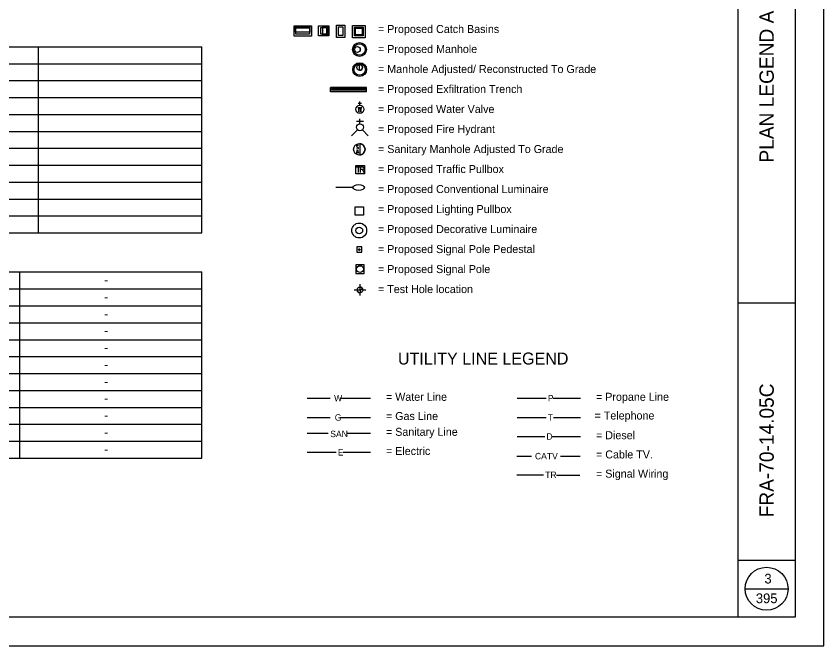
# Model space of a CAD drawing. Extents: x 0 to 34, y 0 to 22.
# Drawn here: x 19.88 to 34, y 0 to 11.02 of the extents above; entities that cross this region are included whole.
import ezdxf

# ---------------------------------------------------------------- set-up
doc = ezdxf.new("R2010")
doc.units = 0
for name, color, linetype in [('Default', 7, 'Continuous'), ('DR_P_Cells', 7, 'Continuous'), ('DR_P_Storm_Sewer', 7, 'Continuous'), ('LT_P_Luminaires', 7, 'Continuous'), ('SG_P_Poles', 7, 'Continuous'), ('SG_P_PullBox', 7, 'Continuous'), ('SH_Border', 7, 'Continuous'), ('SH_Cut_Line', 7, 'Continuous'), ('SH_Data', 7, 'Continuous'), ('SH_Text', 7, 'Continuous'), ('TX_P_5', 7, 'Continuous'), ('TX_P_Misc', 7, 'Continuous'), ('UT_P_Sanitary_Cells', 7, 'Continuous'), ('UT_P_Water_Cells', 7, 'Continuous')]:
    doc.layers.add(name, color=color, linetype=linetype)

msp = doc.modelspace()

# ---------------------------------------------------------------- linework, layer by layer
at = {"layer": 'Default'}
for p, q in [((24.969, 4.334), (25.372, 4.334)), ((25.547, 4.334), (26.075, 4.334)), ((28.641, 4.333), (29.147, 4.333)), ((29.271, 4.333), (29.747, 4.333)), ((24.969, 3.998), (25.372, 3.998)), ((25.547, 3.998), (26.075, 3.998)), ((28.641, 3.997), (29.145, 3.997)), ((29.272, 3.997), (29.747, 3.997)), ((24.969, 3.722), (25.334, 3.722)), ((25.672, 3.722), (26.075, 3.722)), ((28.641, 3.663), (29.122, 3.663)), ((29.245, 3.663), (29.747, 3.663)), ((24.969, 3.386), (25.474, 3.386)), ((25.597, 3.386), (26.075, 3.386)), ((28.633, 3.32), (28.889, 3.32)), ((29.394, 3.32), (29.739, 3.32)), ((28.634, 2.994), (29.101, 2.994)), ((29.329, 2.989), (29.736, 2.989))]:
    msp.add_line(p, q, dxfattribs=at)
msp.add_lwpolyline([(25.805, 7.683), (25.955, 7.683), (25.955, 7.533), (25.805, 7.533)], close=True, dxfattribs=at)
at = {"layer": 'DR_P_Cells'}
for p, q in [((24.773, 10.777), (24.773, 10.814)), ((24.773, 10.814), (24.833, 10.814)), ((24.773, 10.758), (24.773, 10.758)), ((24.871, 10.814), (24.913, 10.814)), ((24.892, 10.848), (24.892, 10.848)), ((24.892, 10.814), (24.892, 10.814)), ((24.892, 10.758), (24.892, 10.758)), ((24.892, 10.739), (24.892, 10.739)), ((24.892, 10.739), (24.892, 10.739)), ((24.951, 10.814), (25.011, 10.814)), ((25.011, 10.814), (25.011, 10.777)), ((25.011, 10.758), (25.011, 10.758)), ((25.169, 10.759), (25.169, 10.759)), ((25.203, 10.759), (25.203, 10.759)), ((25.24, 10.759), (25.24, 10.759)), ((25.24, 10.759), (25.24, 10.759)), ((25.259, 10.814), (25.259, 10.814)), ((25.259, 10.759), (25.259, 10.759)), ((25.259, 10.759), (25.259, 10.759)), ((25.315, 10.759), (25.315, 10.759)), ((25.349, 10.759), (25.349, 10.759)), ((25.483, 10.754), (25.483, 10.754)), ((25.516, 10.754), (25.516, 10.754)), ((25.516, 10.754), (25.516, 10.754)), ((25.516, 10.754), (25.516, 10.754)), ((25.554, 10.829), (25.554, 10.829)), ((25.554, 10.754), (25.554, 10.754)), ((25.591, 10.754), (25.591, 10.754)), ((25.624, 10.754), (25.624, 10.754)), ((25.763, 10.747), (25.763, 10.747)), ((25.796, 10.747), (25.796, 10.747)), ((25.871, 10.822), (25.871, 10.822)), ((25.871, 10.747), (25.871, 10.747)), ((25.871, 10.747), (25.871, 10.747)), ((25.871, 10.747), (25.871, 10.747)), ((25.946, 10.747), (25.946, 10.747)), ((25.98, 10.747), (25.98, 10.747)), ((24.892, 10.702), (24.892, 10.702)), ((24.892, 10.669), (24.892, 10.669)), ((25.259, 10.705), (25.259, 10.705)), ((25.554, 10.679), (25.554, 10.679)), ((25.871, 10.672), (25.871, 10.672)), ((25.783, 10.433), (25.783, 10.433)), ((25.846, 10.434), (25.846, 10.434)), ((25.883, 10.434), (25.883, 10.434)), ((25.883, 10.434), (25.883, 10.434)), ((25.983, 10.436), (25.983, 10.436)), ((25.886, 10.182), (25.886, 10.182)), ((25.886, 10.07), (25.886, 10.17)), ((25.886, 10.12), (25.886, 10.12)), ((25.886, 10.082), (25.886, 10.082)), ((25.886, 10.082), (25.886, 10.082)), ((25.886, 9.982), (25.886, 9.982))]:
    msp.add_line(p, q, dxfattribs=at)
for points in [[(25.044, 10.669), (24.74, 10.669), (24.74, 10.848), (25.044, 10.848)], [(25.017, 10.739), (24.767, 10.739), (24.767, 10.831), (25.017, 10.831)], [(25.011, 10.702), (24.773, 10.702), (24.773, 10.814), (25.011, 10.814)], [(25.169, 10.672), (25.169, 10.847), (25.349, 10.847), (25.349, 10.672)], [(25.203, 10.814), (25.203, 10.705), (25.315, 10.705), (25.315, 10.814)], [(25.24, 10.689), (25.24, 10.83), (25.332, 10.83), (25.332, 10.689)], [(25.483, 10.646), (25.483, 10.862), (25.624, 10.862), (25.624, 10.646)], [(25.516, 10.679), (25.516, 10.829), (25.591, 10.829), (25.591, 10.679)], [(25.516, 10.679), (25.516, 10.829), (25.591, 10.829), (25.591, 10.679)], [(25.516, 10.679), (25.516, 10.829), (25.591, 10.829), (25.591, 10.679)], [(25.763, 10.638), (25.763, 10.855), (25.98, 10.855), (25.98, 10.638)], [(25.796, 10.672), (25.796, 10.822), (25.946, 10.822), (25.946, 10.672)], [(25.814, 10.689), (25.814, 10.804), (25.929, 10.804), (25.929, 10.689)]]:
    msp.add_lwpolyline(points, close=True, dxfattribs=at)
for centre, radius in [((25.883, 10.434), 0.121), ((25.883, 10.434), 0.1), ((25.883, 10.434), 0.1), ((25.846, 10.434), 0.05), ((25.886, 10.082), 0.121), ((25.886, 10.082), 0.1), ((25.886, 10.082), 0.1), ((25.886, 10.12), 0.05)]:
    msp.add_circle(centre, radius, dxfattribs=at)
msp.add_arc((25.886, 10.12), 0.05, 270, 90, dxfattribs=at)
at = {"layer": 'DR_P_Storm_Sewer'}
for p, q in [((26.007, 9.77), (25.374, 9.77)), ((25.374, 9.695), (25.374, 9.77)), ((26.007, 9.695), (26.007, 9.77)), ((26.007, 9.695), (25.374, 9.695)), ((25.991, 9.72), (25.391, 9.72)), ((25.991, 9.72), (25.624, 9.72))]:
    msp.add_line(p, q, dxfattribs=at)
msp.add_lwpolyline([(25.991, 9.753), (25.991, 9.72), (25.391, 9.72), (25.391, 9.753)], close=True, dxfattribs=at)
at = {"layer": 'LT_P_Luminaires'}
msp.add_line((25.769, 8.019), (25.469, 8.019), dxfattribs=at)
for radius in [0.13, 0.06]:
    msp.add_circle((25.878, 7.267), radius, dxfattribs=at)
msp.add_ellipse((25.869, 8.019), major_axis=(-0.1, 0), ratio=0.5, dxfattribs=at)
msp.add_ellipse((25.869, 8.019), major_axis=(-0.1, 0), ratio=0.5, dxfattribs=at)
at = {"layer": 'SG_P_Poles'}
for points in [[(25.836, 6.889), (25.926, 6.889), (25.926, 6.979), (25.836, 6.979)], [(25.817, 6.516), (25.967, 6.516), (25.967, 6.666), (25.817, 6.666)]]:
    msp.add_lwpolyline(points, close=True, dxfattribs=at)
for centre, radius in [((25.881, 6.934), 0.015), ((25.892, 6.591), 0.06)]:
    msp.add_circle(centre, radius, dxfattribs=at)
at = {"layer": 'SG_P_PullBox'}
msp.add_line((25.895, 8.331), (25.895, 8.331), dxfattribs=at)
msp.add_lwpolyline([(25.82, 8.406), (25.97, 8.406), (25.97, 8.256), (25.82, 8.256)], close=True, dxfattribs=at)
for points in [[(25.827, 8.381), (25.889, 8.381)], [(25.858, 8.381), (25.858, 8.281)], [(25.9, 8.281), (25.9, 8.381), (25.938, 8.381), (25.942, 8.38), (25.947, 8.379), (25.95, 8.377), (25.952, 8.375), (25.955, 8.371), (25.958, 8.368), (25.959, 8.361), (25.959, 8.352), (25.958, 8.349), (25.957, 8.344), (25.954, 8.338), (25.951, 8.336), (25.948, 8.334), (25.947, 8.334), (25.944, 8.333), (25.937, 8.332), (25.9, 8.332)], [(25.937, 8.332), (25.959, 8.281)]]:
    msp.add_lwpolyline(points, dxfattribs=at)
at = {"layer": 'SH_Border'}
for p, q in [((32.5, 0.5), (32.5, 21.5)), ((32.5, 6), (33.5, 6)), ((32.5, 1.5), (33.5, 1.5))]:
    msp.add_line(p, q, dxfattribs=at)
msp.add_lwpolyline([(2, 21.5), (33.5, 21.5), (33.5, 0.5), (2, 0.5)], close=True, dxfattribs=at)
at = {"layer": 'SH_Cut_Line'}
msp.add_lwpolyline([(0, 0), (34, 0), (34, 22), (0, 22)], close=True, dxfattribs=at)
at = {"layer": 'SH_Data'}
msp.add_line((32.625, 1), (33.375, 1), dxfattribs=at)
msp.add_circle((33, 1), 0.375, dxfattribs=at)
at = {"layer": 'TX_P_5'}
for p, q in [((8.165, 10.481), (23.127, 10.481)), ((20.27, 7.225), (20.27, 10.481)), ((23.127, 7.225), (23.127, 10.481)), ((8.165, 10.185), (23.127, 10.185)), ((8.165, 9.889), (23.127, 9.889)), ((8.165, 9.593), (23.127, 9.593)), ((8.165, 9.297), (23.127, 9.297)), ((8.165, 9.001), (23.127, 9.001)), ((8.165, 8.705), (23.127, 8.705)), ((8.165, 8.409), (23.127, 8.409)), ((8.165, 8.113), (23.127, 8.113)), ((8.165, 7.817), (23.127, 7.817)), ((8.165, 7.521), (23.127, 7.521)), ((8.165, 7.225), (23.127, 7.225)), ((8.165, 6.541), (23.127, 6.541)), ((19.946, 3.285), (19.946, 6.541)), ((23.127, 3.285), (23.127, 6.541)), ((8.165, 6.245), (23.127, 6.245)), ((8.165, 5.949), (23.127, 5.949)), ((8.165, 5.653), (23.127, 5.653)), ((8.165, 5.357), (23.127, 5.357)), ((8.165, 5.061), (23.127, 5.061)), ((8.165, 4.765), (23.127, 4.765)), ((8.165, 4.469), (23.127, 4.469)), ((8.165, 4.173), (23.127, 4.173)), ((8.165, 3.877), (23.127, 3.877)), ((8.165, 3.581), (23.127, 3.581)), ((8.165, 3.285), (23.127, 3.285))]:
    msp.add_line(p, q, dxfattribs=at)
at = {"layer": 'TX_P_Misc'}
for p, q in [((25.791, 6.227), (25.841, 6.227)), ((25.841, 6.227), (25.892, 6.227)), ((25.892, 6.277), (25.892, 6.327)), ((25.892, 6.227), (25.892, 6.277)), ((25.892, 6.227), (25.892, 6.177)), ((25.941, 6.227), (25.892, 6.227)), ((25.941, 6.227), (25.991, 6.227)), ((25.892, 6.127), (25.892, 6.177))]:
    msp.add_line(p, q, dxfattribs=at)
msp.add_circle((25.892, 6.227), 0.05, dxfattribs=at)
for start, end in [(179.7135, 270.2865), (0.2865, 89.7135)]:
    msp.add_arc((25.891, 6.227), 0.05, start, end, dxfattribs=at)
at = {"layer": 'UT_P_Sanitary_Cells'}
for p, q in [((25.89, 8.787), (25.89, 8.588)), ((25.833, 8.633), (25.862, 8.633)), ((25.835, 8.734), (25.862, 8.72))]:
    msp.add_line(p, q, dxfattribs=at)
msp.add_lwpolyline([(25.828, 8.618), (25.847, 8.678), (25.867, 8.618)], dxfattribs=at)
msp.add_circle((25.88, 8.687), 0.1, dxfattribs=at)
for centre, radius, start, end in [((25.849, 8.724), 0.0314, 61.3463, 118.6537), ((25.88, 8.687), 0.1, 275.7389, 84.2597), ((25.841, 8.743), 0.0106, 126.2587, 236.3675), ((25.848, 8.721), 0.0249, 223.6695, 304.3963), ((25.853, 8.71), 0.0133, 311.4883, 47.9358)]:
    msp.add_arc(centre, radius, start, end, dxfattribs=at)
at = {"layer": 'UT_P_Water_Cells'}
for p, q in [((25.921, 9.489), (25.858, 9.489)), ((25.889, 9.457), (25.889, 9.521)), ((25.891, 9.132), (25.891, 9.218)), ((25.951, 9.175), (25.831, 9.175)), ((25.849, 9.029), (25.745, 8.925)), ((25.933, 9.029), (26.037, 8.925))]:
    msp.add_line(p, q, dxfattribs=at)
msp.add_lwpolyline([(25.858, 9.427), (25.874, 9.341), (25.889, 9.427), (25.905, 9.341), (25.921, 9.427)], dxfattribs=at)
for centre, radius in [((25.889, 9.387), 0.07), ((25.891, 9.072), 0.06)]:
    msp.add_circle(centre, radius, dxfattribs=at)

# ---------------------------------------------------------------- texts
at = {"layer": 'Default'}
for s, p in [('W', (25.439, 4.276)), ('P', (29.175, 4.277)), ('G', (25.451, 3.94)), ('T', (29.173, 3.941)), ('SAN', (25.372, 3.652)), ('D', (29.15, 3.607)), ('E', (25.504, 3.33)), ('CATV', (28.95, 3.264)), ('TR', (29.129, 2.936))]:
    msp.add_text(s, height=0.112, dxfattribs=at).set_placement(p)
at = {"layer": 'SH_Data'}
for s, p in [('PLAN LEGEND AND DESIGN DESIGNATIONS', (33.125, 8.456)), ('FRA-70-14.05C ', (33.125, 2.249))]:
    msp.add_text(s, height=0.25, rotation=90, dxfattribs=at).set_placement(p)
for s, p in [('3', (32.961, 1.091)), ('395', (32.811, 0.747))]:
    msp.add_text(s, height=0.17, dxfattribs=at).set_placement(p)
at = {"layer": 'SH_Text'}
for s, p in [('= Proposed Catch Basins', (26.207, 10.722)), ('= Proposed Manhole', (26.207, 10.372)), ('= Manhole Adjusted/ Reconstructed To Grade', (26.207, 10.022)), ('= Proposed Exfiltration Trench', (26.207, 9.672)), ('= Proposed Water Valve', (26.207, 9.322)), ('= Proposed Fire Hydrant', (26.207, 8.972)), ('= Sanitary Manhole Adjusted To Grade', (26.207, 8.622)), ('= Proposed Traffic Pullbox', (26.207, 8.272)), ('= Proposed Conventional Luminaire', (26.207, 7.922)), ('= Proposed Lighting Pullbox', (26.207, 7.572)), ('= Proposed Decorative Luminaire', (26.207, 7.222)), ('= Proposed Signal Pole Pedestal', (26.207, 6.872)), ('= Proposed Signal Pole', (26.207, 6.522)), ('= Test Hole location', (26.207, 6.172)), ('= Water Line', (26.346, 4.287)), ('= Propane Line', (30.018, 4.287)), ('= Gas Line', (26.346, 3.951)), ('= Telephone', (29.992, 3.96)), ('= Sanitary Line', (26.346, 3.675)), ('= Diesel', (30.018, 3.615)), ('= Electric', (26.346, 3.339)), ('= Cable TV.', (30.018, 3.279)), ('= Signal Wiring', (30.018, 2.943))]:
    msp.add_text(s, height=0.14, dxfattribs=at).set_placement(p)
msp.add_text('UTILITY LINE LEGEND', height=0.21, rotation=0, dxfattribs=at).set_placement((26.555, 4.922))
at = {"layer": 'TX_P_5'}
for p in [(21.418, 6.326), (21.418, 6.03), (21.418, 5.734), (21.418, 5.438), (21.418, 5.142), (21.418, 4.846), (21.418, 4.55), (21.418, 4.254), (21.418, 3.958), (21.418, 3.662), (21.418, 3.366)]:
    msp.add_text('-', height=0.156, dxfattribs=at).set_placement(p)

doc.saveas('drawing.dxf')
